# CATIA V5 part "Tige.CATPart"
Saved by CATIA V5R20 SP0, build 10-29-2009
Part number: Tige
Bounding box of the stored display mesh (mm): x -40 to 0, y 36.898 to 171.198, z -19.953 to 19.953
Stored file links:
  F:\Catia_finish\Tige.CATPart
  F:\Catia_finish\ASS_compresseur.CATProduct
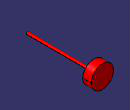
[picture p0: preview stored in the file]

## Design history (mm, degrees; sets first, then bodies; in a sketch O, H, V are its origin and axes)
External parameters (linked from other documents)
  External.longueur_tige = 119.3 mm
  External.excentricite_vilebrequin = 6 mm
  External.longueur_bielle = 35 mm
  External.rayon_piston = 20 mm
Set1
  Plane1: linked copy from another document
  Point1: linked copy from another document
  Line1: linked copy from another document
  Point2: linked copy from another document
Body1 (main body)
  Sketch1 on Plane1, origin (0, 156.1983, 0), H (-1, 0, 0), V (0, 0, 1)
    circle A1 centre (20, 0) radius 20
    point P1 (20, 0)
    reference projected point E1 (20, 0) from Point1
    radius A1 = 20 {= External.rayon_piston}
    coincidence: P1 E1
  Pad1: profile Sketch1, direction (0, 1, 0), length 15
  Sketch2 on start face of Pad1, origin (0, 156.1983, 0), H (1, 0, 0), V (0, 0, 1)
    circle A1 centre (-20, 0) radius 2.5
    point P1 (-20, 0)
    reference projected point E1 (-20, 0) from Point1
    radius A1 = 2.5
    coincidence: P1 E1
  Pad2: profile Sketch2, direction (0, -1, 0), length 119.3 {= External.longueur_tige}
